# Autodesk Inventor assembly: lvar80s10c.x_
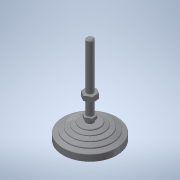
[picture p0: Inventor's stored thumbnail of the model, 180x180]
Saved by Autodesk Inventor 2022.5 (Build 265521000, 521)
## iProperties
Part Number: lvar80s10c.x_
Material: 一般
Document SubType Name: Assembly
Designer: ImaoCorp
Sending System: SOLIDWORKS 2017-2017317
MC: AMD64
MC_MODEL: Intel64 Family 6 Model 60 Stepping 3, GenuineIntel
OS: Windows_NT
FRU: Parasolid Version 29.0, build 201,  4-17-2017
FORMAT: text
GUISE: transmit
KEY: lvar80s10c
FILE: lvar80s10c.x_t
DATE: Mon Jul 01 18:15:38 2019
Author: ImaoCorp
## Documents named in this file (3)
- X:\14_SW2022-Inv2022\00_全2023-1023新製品(TCC)まで\l\lvar80s10c\LVAR80S10C.iam
- X:\14_SW2022-Inv2022\00_全2023-1023新製品(TCC)まで\l\lvar80s10c\lvar80s10c_01.ipt
- X:\14_SW2022-Inv2022\00_全2023-1023新製品(TCC)まで\l\lvar80s10c\lvar80s10c_02.ipt
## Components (2 placed, 2 different names)
1. lvar80s10c_01
2. lvar80s10c_02
